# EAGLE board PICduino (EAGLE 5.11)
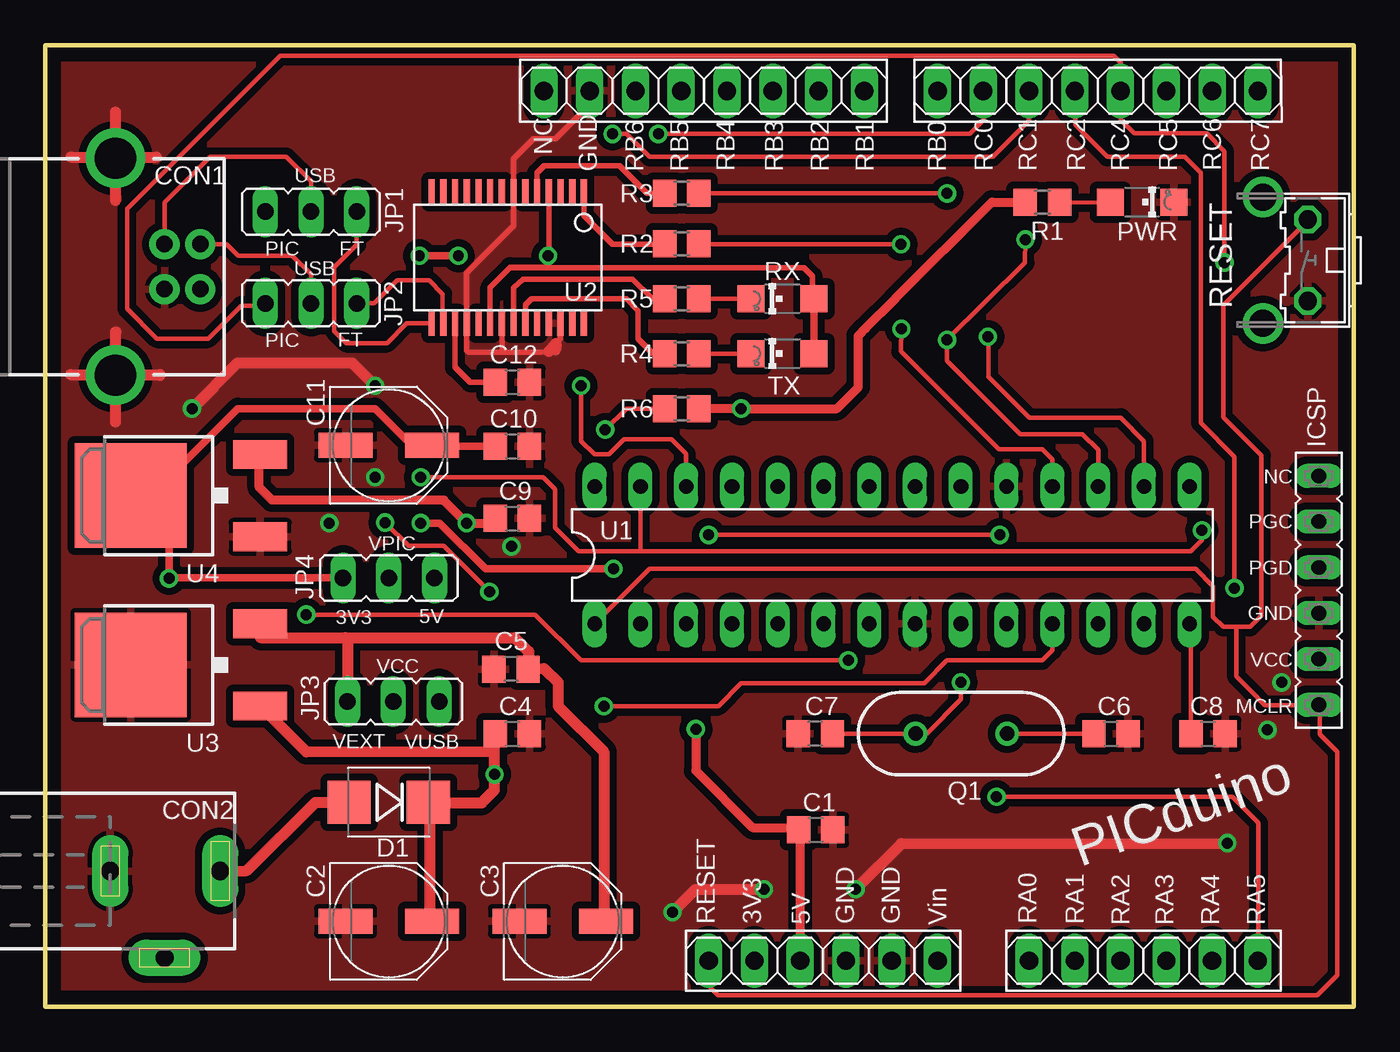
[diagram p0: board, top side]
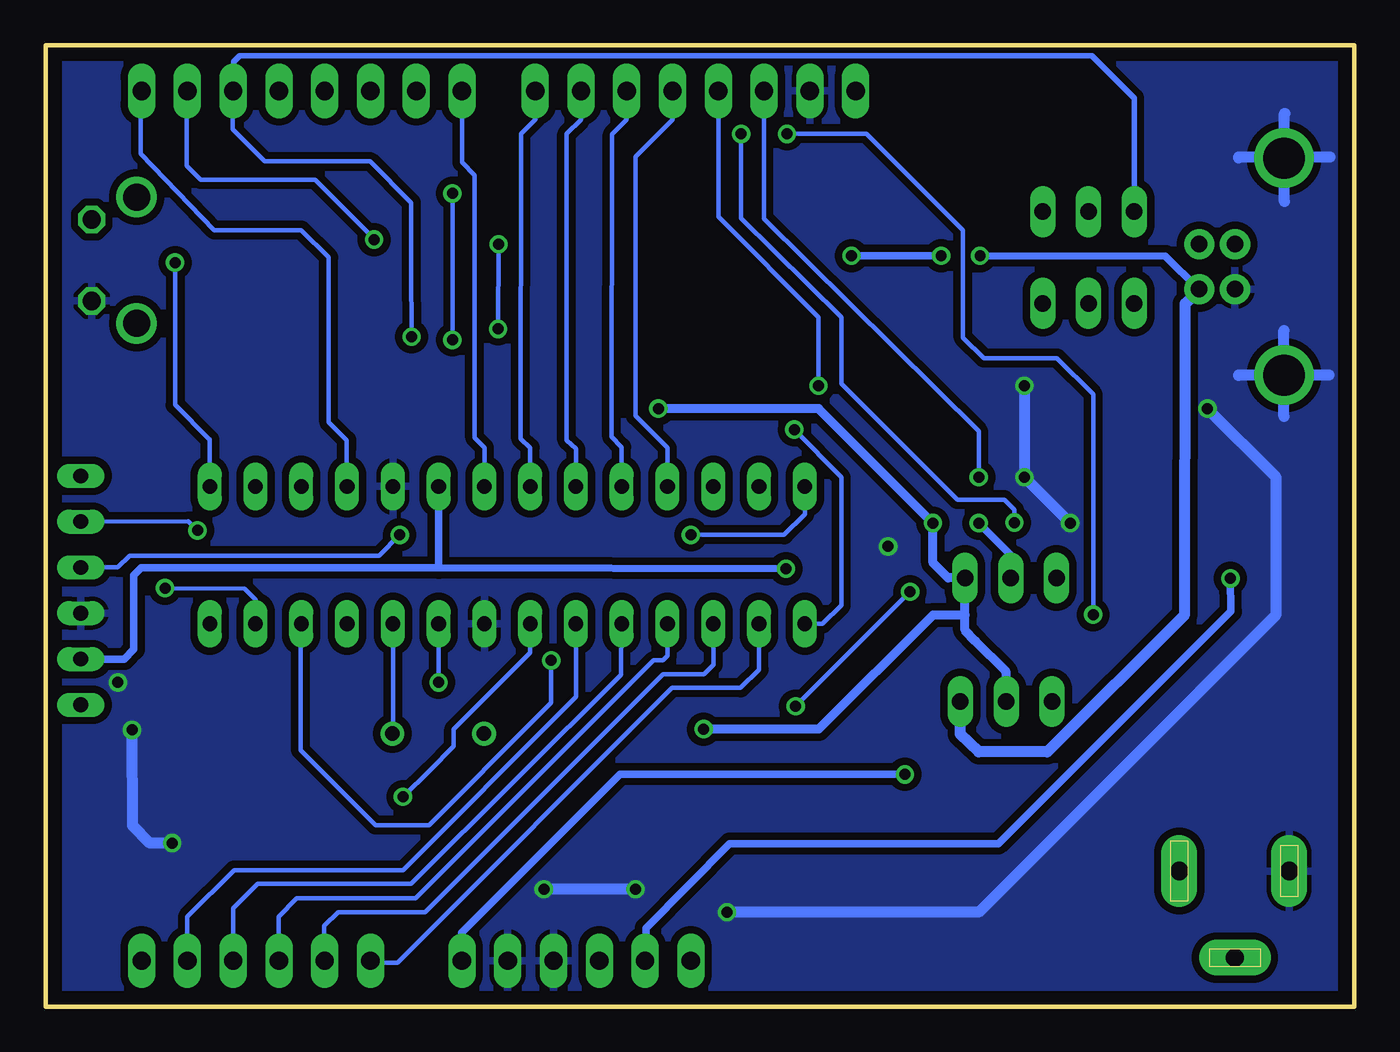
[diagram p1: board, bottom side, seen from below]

Size 72.64 x 53.34 mm. Coordinates in mm from the lower left corner, seen from the top.
Outline: 0,53.34 72.64,53.34 72.64,0 0,0 0,53.34
Copper layers (1*16): Top 0.035mm / dielectric 1.5mm / Bottom 0.035mm
Design rules "default *": minimum track width 10mil, minimum drill 16mil, track to track 8mil, track to pad 8mil, pad to pad 8mil, via to via 8mil, smd to smd 8mil, copper to edge 30mil, drill to drill 8mil, minimum pad ring 10mil, minimum via ring 8mil, stop-mask expansion 4mil, vias tented up to drill 0mil, thermal gap 10mil
Net classes: 0 default: width 0.254 mm, drill 0.305 mm, clearance 0.152 mm; 1 power: width 0.61 mm, drill 0.508 mm, clearance 0.152 mm; 2 gnd: width 0.305 mm, drill 0.508 mm, clearance 0.152 mm; 3 usbvcc: width 0.508 mm, drill 0.508 mm, clearance 0.152 mm; 4 aref: width 0.406 mm

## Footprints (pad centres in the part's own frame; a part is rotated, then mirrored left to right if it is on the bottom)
C0805 = smd 1.3 x 1.5: 1 -0.95,0; 2 0.95,0
PANASONIC_D = smd 3 x 1.4: + 2.4,0; - -2.4,0
USB-B-PTH = drill 0.914 pad 1.676 round: D+ 0,1.25; D- 1.981,1.25; GND 0,-1.25; VBUS 1.981,-1.25 | drill 2.286 round: P$1 -2.718,-6.02; P$2 -2.718,6.02
DCJ0202 = drill 1 pad 2 long: 1 0,3.1; 2 4.8,0; 3 0,-3
SMB-DIODE = smd 2.4 x 2.4: A 2.2,0; C -2.2,0
FE06 = drill 0.813 long: 1 -6.35,0; 2 -3.81,0; 3 -1.27,0; 4 1.27,0; 5 3.81,0; 6 6.35,0
1X08 = drill 1.016 long: 1 -8.89,0; 2 -6.35,0; 3 -3.81,0; 4 -1.27,0; 5 1.27,0; 6 3.81,0; 7 6.35,0; 8 8.89,0
1X06 = drill 1.016 long: 1 -6.35,0; 2 -3.81,0; 3 -1.27,0; 4 1.27,0; 5 3.81,0; 6 6.35,0
JP2 = drill 0.914 long: 1 -2.54,0; 2 0,0; 3 2.54,0
CHIPLED_1206 = smd 1.5 x 1.5: A 0,-1.75; C 0,1.75
HC49US = drill 0.813 round: 1 -2.54,0; 2 2.54,0
R0805 = smd 1.3 x 1.5: 1 -0.95,0; 2 0.95,0
B3F-31XX = drill 1.016 octagon: 1 -2.261,-1.245; 2 2.261,-1.245 | drill 1.499 pad 2.159 round: 3 -3.505,1.245; 4 3.505,1.245
DIL28-3 = drill 0.813 long: 1 -16.51,-3.81; 2 -13.97,-3.81; 3 -11.43,-3.81; 4 -8.89,-3.81; 5 -6.35,-3.81; 6 -3.81,-3.81; 7 -1.27,-3.81; 8 1.27,-3.81; 9 3.81,-3.81; 10 6.35,-3.81; 11 8.89,-3.81; 12 11.43,-3.81; 13 13.97,-3.81; 14 16.51,-3.81; 15 16.51,3.81; 16 13.97,3.81; 17 11.43,3.81; 18 8.89,3.81; 19 6.35,3.81; 20 3.81,3.81; 21 1.27,3.81; 22 -1.27,3.81; 23 -3.81,3.81; 24 -6.35,3.81; 25 -8.89,3.81; 26 -11.43,3.81; 27 -13.97,3.81; 28 -16.51,3.81
SSOP28DB = smd 0.348 x 1.397: 1 -4.225,-3.656; 2 -3.575,-3.656; 3 -2.925,-3.656; 4 -2.275,-3.656; 5 -1.625,-3.656; 6 -0.975,-3.656; 7 -0.325,-3.656; 8 0.325,-3.656; 9 0.975,-3.656; 10 1.625,-3.656; 11 2.275,-3.656; 12 2.925,-3.656; 13 3.575,-3.656; 14 4.225,-3.656; 15 4.225,3.656; 16 3.575,3.656; 17 2.925,3.656; 18 2.275,3.656; 19 1.625,3.656; 20 0.975,3.656; 21 0.325,3.656; 22 -0.325,3.656; 23 -0.975,3.656; 24 -1.625,3.656; 25 -2.275,3.656; 26 -2.925,3.656; 27 -3.575,3.656; 28 -4.225,3.656
DPACK = smd 1.6 x 3: 1 -2.28,-4.8; 3 2.28,-4.8 | smd 5.8 x 6.2: 4 0,2.38

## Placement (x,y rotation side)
C1  100nF  [C0805]  42.77,9.8 0 top
C2  [PANASONIC_D]  19.08,4.72 0 top
C3  [PANASONIC_D]  28.73,4.72 0 top
C4  100nF  [C0805]  25.93,15.14 0 top
C5  100nF  [C0805]  25.86,18.72 180 top
C6  15pF  [C0805]  59.16,15.14 0 top
C7  15pF  [C0805]  42.75,15.14 180 top
C8  100nF  [C0805]  64.54,15.14 0 top
C9  100nF  [C0805]  25.93,27.08 0 top
C10  100nF  [C0805]  25.93,31.09 0 top
C11  [PANASONIC_D]  19.08,31.14 0 top
C12  100nF  [C0805]  25.93,34.65 0 top
CON1  USBPTH  [USB-B-PTH]  6.63,41.05 0 top
CON2  DCJ0202  [DCJ0202]  6.63,7.52 270 top
D1  MBRS130  [SMB-DIODE]  19.08,11.33 180 top
ICSP  [FE06]  70.69,23.09 90 top
J1  [1X08]  58.42,50.8 180 top
J2  [1X06]  60.96,2.54 0 top
J3  [1X08]  36.58,50.8 180 top
JP1  [JP2]  14.76,44.09 180 top
JP2  [JP2]  14.76,39.01 180 top
JP3  [JP2]  19.33,16.92 180 top
JP4  [JP2]  19.08,23.77 0 top
POWER  [1X06]  43.18,2.54 0 top
PWR  [CHIPLED_1206]  60.88,44.63 270 top
Q1  [HC49US]  50.85,15.14 0 top
R1  1k  [R0805]  55.35,44.63 180 top
R2  1k  [R0805]  35.33,42.32 0 top
R3  1k  [R0805]  35.33,45.11 0 top
R4  1k  [R0805]  35.33,36.22 0 top
R5  1k  [R0805]  35.33,39.27 0 top
R6  10k  [R0805]  35.33,33.17 180 top
RESET  RESET  [B3F-31XX]  68.83,41.4 90 top
RX  [CHIPLED_1206]  40.92,39.27 90 top
TX  [CHIPLED_1206]  40.92,36.22 90 top
U1  PIC18F2550_28DIP  [DIL28-3]  47.02,25.04 0 top
U2  FT232RL-BASICSSOP  [SSOP28DB]  25.68,41.55 180 top
U3  LP2950CDT-5.0  [DPACK]  7.14,18.95 90 top
U4  3V3  [DPACK]  7.14,28.35 90 top

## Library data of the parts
C1-C12 R1-R6 = rcl
CON1 D1 Q1 U2 = moja
CON2 = con-jack; OC_FARNELL: unknown; OC_NEWARK: unknown
ICSP = con-lsta; OC_FARNELL: unknown; OC_NEWARK: unknown
J1-J3 POWER = pinhead
JP1-JP4 = jumper
PWR RX TX = led
RESET = switch-omron; MPN: B3F-3100; OC_FARNELL: 959704; OC_NEWARK: 36M3582
U1 = microchip; MF: MICROCHIP; MPN: PIC18F2550-I/SP; OC_FARNELL: 1523822; OC_NEWARK: 80K6054
U3 U4 = v-reg

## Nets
3V3: C10.1 C11.+ JP4.1 POWER.2 U4.4
+5V [usbvcc]: C1.1 C9.1 JP3.2 JP4.3 POWER.3 R6.1 U4.3
AREF: J3.8
D+FT: JP1.1 U2.15
D-FT: JP2.1 U2.16
GND [power]: C1.2 C2.- C3.- C4.2 C5.2 C6.2 C7.2 C8.2 C9.2 C10.2 C11.- C12.2 CON1.GND CON2.3 ICSP.3 J3.7 POWER.4 POWER.5 PWR.C RESET.1 U1.8 U1.19 U2.7 U2.18 U2.21 U2.25 U2.26 U3.4 U4.1
MCLR: ICSP.1 POWER.1 R6.2 RESET.2 U1.1
N$1: C8.1 U1.14
N$2: CON2.1 D1.A
N$3: C3.+ C5.1 JP3.3 U3.3
N$4: CON1.D+ JP1.2
N$5: CON1.D- JP2.2
N$6: R2.1 U2.1
N$8: PWR.A R1.1
N$9: R3.1 U2.5
N$11: R4.1 U2.23
N$12: R5.1 U2.22
N$13: R4.2 TX.C
N$14: C12.1 U2.17
N$15: R5.2 RX.C
RA0: J2.1 U1.2
RA1: J2.2 U1.3
RA2: J2.3 U1.4
RA3: J2.4 U1.5
RA4: J2.5 U1.6
RA5: J2.6 U1.7
RB0: J1.8 U1.21
RB1: J3.1 U1.22
RB2: J3.2 U1.23
RB3: J3.3 U1.24
RB4: J3.4 U1.25
RB5: J3.5 U1.26
RB6: ICSP.5 J3.6 U1.27
RB7: ICSP.4 U1.28
RC0: J1.7 U1.11
RC1: J1.6 U1.12
RC2: J1.5 U1.13
RC4: J1.4 JP2.3 U1.15
RC5: J1.3 JP1.3 U1.16
RC6: J1.2 R3.2 U1.17
RC7: J1.1 R2.2 U1.18
S$2 [usbvcc]: RX.A U2.4 U2.20
S$3 [usbvcc]: R1.2
VCC: ICSP.2 JP4.2 U1.20
VIN: C2.+ C4.1 D1.C POWER.6 U3.1
VUSB: CON1.VBUS JP3.1
X1: C7.1 Q1.1 U1.9
X2: C6.1 Q1.2 U1.10

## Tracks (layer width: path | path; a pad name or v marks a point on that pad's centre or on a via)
3V3  (via drill 0.61)
  Top 0.254: 6.88,26.49 4.34,28.09 U4.4 5.61,28.09 | 20.85,30.63 C11.+
  Top 0.406: 6.88,23.77 6.88,26.49 | 6.88,23.77 JP4.1 | v6.88,23.75 6.88,23.77 | 20.85,30.63 18.31,33.17 10.69,33.17 5.61,28.09 | C10.1 21.53,31.09 C11.+
  Bottom 0.406: v6.88,23.75 6.86,21.92 19.76,9.04 34.67,9.04 39.32,4.34 39.32,3.07 POWER.2
+5V  (via drill 0.61)
  Top 0.508: U4.3 10.69,30.63 11.86,30.61 11.89,30.58 11.89,28.8 12.6,28.09 22.12,28.09 v23.39,26.82 24.66,26.82 C9.1 | 36.09,33.17 R6.1 v38.63,33.17 43.94,33.17 45.14,34.37 45.14,37.21 45.54,37.62 47.17,39.24 | POWER.3 41.88,2.31 41.88,9.93 | 41.88,9.93 C1.1 | 41.88,9.93 39.27,9.93 36.12,13.08 v36.12,15.39
  Bottom 0.508: v38.63,33.17 29.74,33.17 v23.39,26.82 23.39,24.61 22.56,23.77 JP4.3 21.62,21.72 | v36.12,15.39 29.74,15.39 23.39,21.72 21.62,21.72 | 21.62,21.72 21.62,20.88 21.03,20.27 19.38,18.62 19.33,18.54 JP3.2
D+FT
  Top 0.254: JP1.1 17.3,42.27 16.05,41.02 16.05,37.47 16.71,36.8 18.97,36.8 20.07,37.9 U2.15
D-FT
  Top 0.254: JP2.1 18.26,39.01 19.53,40.28 21.31,40.28 22.07,39.52 22.07,37.93 U2.16
GND  (via drill 0.61)
  Top 0.305: J3.7 30.2,50.77 30.23,50.7 29.9,49.68 28.32,48.13 27.1,48.13 26,47.04 U2.7 26,43.33 23.39,40.72 U2.18 23.4,36.39 23.5,36.3 25.37,36.3 | 25.37,36.3 27.51,36.3 27.95,36.34 | U2.21 25.35,36.32 25.37,36.3 | U2.26 28.6,37.04 28.35,36.78
  Top 0.61: v18.31,34.44 17.04,35.71 10.69,35.71 v8.15,33.17 | v34.82,5.23 36.09,6.5 v39.9,6.5 | v44.98,6.5 47.52,9.04 v65.61,9.07 | 28.32,36.42 28.35,36.78 27.95,36.34 | 1.45,47.12 6.17,47.12 | 3.91,44.73 3.91,49.63 | 3.94,37.41 3.91,37.41 3.91,32.44 | 1.42,35.05 6.38,35.05 6.38,35
  Bottom 0.61: v15.77,26.82 v18.31,29.36 v18.31,34.44 | v8.15,33.17 4.34,29.36 4.34,21.74 20.85,5.23 v34.82,5.23 | v39.9,6.5 v44.98,6.5 | v65.61,9.07 66.85,9.07 67.82,10.03 v67.84,15.34 | 3.86,49.53 3.89,49.53 3.89,44.65 | 1.35,47.12 6.43,47.12 6.43,47.07 | 3.91,32.74 3.91,37.52 | 1.42,35.03 6.43,35.03 6.43,35
  other vias: 25.88,25.53 68.63,17.98
  pour Top (isolate 0.406): -0.48,54.86 73.69,54 73.69,-0.61 -2.59,-0.46 -3.86,54.81
  pour Bottom (isolate 0.406): -3.1,54.58 73.69,54 73.69,-0.61 -3.51,-0.64
MCLR  (via drill 0.61)
  Top 0.254: v31.09,32 32.28,33.17 R6.2 | 66.12,21.06 66.12,18.31 66.85,17.58 67.69,16.71 70.54,16.71 ICSP.1 70.74,16.69 70.74,15.11 71.7,14.15 71.7,1.73 70.61,0.64 37.34,0.64 36.83,1.14 POWER.1 | U1.1 33.55,24.28 63.86,24.28 64.82,23.32 64.82,21.62 65.38,21.06 66.12,21.06 | RESET.2 70.08,43.59 65.41,38.91 65.41,32.69 67.51,30.58 67.51,21.69 66.88,21.06 66.12,21.06
  Bottom 0.254: v31.09,32 28.47,29.36 28.47,22.25 29.51,21.23 U1.1
N$1
  Top 0.254: C8.1 63.58,15.34 63.58,20.42 U1.14
N$2
  Top 0.254: 16.69,11.33 D1.A
  Top 0.61: 16.69,11.33 15.01,11.33 11.2,7.54 CON2.1
N$3
  Top 0.254: U3.3 11.96,20.47 | 31.01,5.23 C3.+ | 26.85,18.77 C5.1
  Top 0.61: 16.66,20.47 26.06,20.47 26.85,19.69 26.85,18.77 27.69,18.75 28.47,17.98 28.47,16.66 31.01,14.12 31.01,5.23 | 11.96,20.47 16.66,20.47 | 16.66,20.47 16.79,20.35 JP3.3
N$4
  Top 0.254: JP1.2 14.76,45.8 13.39,47.14 9.17,47.14 6.63,44.63 CON1.D+ 6.63,42.06
N$5
  Top 0.254: JP2.2 14.76,40.61 13.72,41.66 10.72,41.66 10.16,42.21 10.08,42.3 CON1.D-
N$6
  Top 0.305: U2.1 29.9,43.88 31.5,42.29 34.36,42.29 R2.1
N$8
  Top 0.254: R1.1 58.72,44.6 PWR.A 58.95,44.68
N$9
  Top 0.305: U2.5 27.3,46.25 27.69,46.63 31.88,46.63 33.4,45.11 R3.1
N$11
  Top 0.305: R4.1 33.73,36.22 32.92,37.03 32.92,38.61 32.26,39.27 27,39.27 26.67,38.94 26.67,37.91 U2.23
N$12
  Top 0.305: R5.1 33.71,39.27 32.61,40.36 26.52,40.36 26.01,39.88 U2.22
N$13
  Top 0.254: 36.27,36.22 R4.2 TX.C
N$14
  Top 0.305: U2.17 22.75,35.46 23.6,34.62 24.96,34.62 C12.1
N$15
  Top 0.254: 36.09,39.27 R5.2 RX.C
RA0
  Bottom 0.254: U1.2 33.05,18.69 34.06,17.68 37.87,17.68 53.11,2.44 54.51,2.44 J2.1
RA1
  Bottom 0.254: U1.3 35.59,18.95 36.09,18.44 38.38,18.44 51.59,5.23 56.41,5.23 57.18,4.47 57.18,2.57 J2.2
RA2
  Bottom 0.254: U1.4 38.13,19.46 38.38,19.2 38.89,19.2 39.14,18.95 52.1,5.99 58.7,5.99 59.72,4.98 59.72,2.57 J2.3
RA3
  Bottom 0.254: U1.5 40.69,18.54 40.72,18.42 52.35,6.81 60.86,6.81 61.19,6.5 62.23,5.46 J2.4
RA4
  Bottom 0.254: U1.6 43.21,17.2 43.71,16.66 52.81,7.57 62.18,7.57 64.77,4.98 J2.5
RA5  (via drill 0.61)
  Top 0.254: v52.81,11.63 65.89,11.63 67.34,10.19 67.34,2.51 67.41,2.57 J2.6
  Bottom 0.254: v52.81,11.63 51.31,13.11 49.99,14.43 49.99,15.39 45.75,19.63 U1.7
RB0
  Bottom 0.254: U1.21 48.29,31.01 48.82,31.55 48.82,46.13 49.53,46.84 J1.8
RB1
  Bottom 0.254: U1.22 45.75,31.01 46.28,31.5 46.25,48.41 45.44,49.23 J3.1
RB2
  Bottom 0.254: U1.23 43.21,30.94 43.71,31.42 43.71,48.41 42.93,49.2 J3.2
RB3
  Bottom 0.254: U1.24 40.67,31.04 41.22,31.6 41.2,48.39 40.39,49.2 J3.3
RB4
  Bottom 0.254: U1.25 38.13,30.99 39.9,32.77 39.9,47.14 37.85,49.2 J3.4
RB5  (via drill 0.61)
  Top 0.254: v29.74,34.44 29.74,31.37 30.51,30.63 31.29,30.63 32.13,31.47 34.77,31.47 35.59,30.66 U1.26
  Bottom 0.254: v29.74,34.44 29.74,38.25 35.31,43.82 J3.5
RB6  (via drill 0.61)
  Top 0.254: 33.05,25.25 U1.27 33.05,28.88 | 33.05,25.25 63.58,25.25 64.19,25.86 v64.21,26.42 | v20.85,29.36 27.64,29.36 28.3,28.7 28.3,26.57 29.62,25.25 33.05,25.25
  Bottom 0.254: v64.21,26.42 64.72,26.92 ICSP.5 | v20.85,29.36 20.85,31.9 32.77,43.71 J3.6
RB7  (via drill 0.61)
  Top 0.254: v36.83,26.16 v52.98,26.16
  Bottom 0.254: v52.98,26.16 54.13,25.02 67.97,25.02 68.63,24.36 ICSP.4 | v36.83,26.16 31.65,26.16 30.51,27.31 U1.28
RC0  (via drill 0.61)
  Top 0.254: v31.01,16.66 37.36,16.66 38.63,17.93 48.79,17.93 50.06,19.2 55.35,19.2 55.91,19.76 U1.11 | v24.66,23.01 22.12,25.55 20.17,25.55 v18.87,26.85 | v34.04,48.41 51.33,48.41 52.07,49.17 J1.7
  Bottom 0.254: v24.66,23.01 v31.01,16.66 | v18.87,26.85 18.87,27.56 19.43,28.12 22.05,28.12 28.47,34.54 28.47,38.25 34.04,43.74 v34.04,48.41
RC1  (via drill 0.61)
  Top 0.254: v44.58,19.2 29.74,19.2 27.2,21.74 v14.5,21.74 | v31.5,48.41 32.28,48.41 33.55,47.14 52.6,47.14 54.61,49.15 J1.6
  Bottom 0.254: v44.58,19.2 44.58,16.87 45.31,16.13 51.36,10.06 54.33,10.06 58.5,14.22 58.5,19.91 U1.12 | v14.5,21.74 14.5,33.96 16.51,35.97 20.57,35.97 21.72,37.11 21.72,43.05 27.08,48.41 v31.5,48.41
RC2  (via drill 0.61)
  Top 0.254: v66.01,23.22 66.01,30.51 64.14,32.39 64.14,46.25 63.25,47.14 58.95,47.14 57.18,48.92 J1.5
  Bottom 0.254: v66.01,23.22 61.6,23.19 60.99,22.58 U1.13
RC4  (via drill 0.61)
  Top 0.254: v65.46,41.28 65.46,47.45 64.47,48.44 60.45,48.44 59.72,49.17 J1.4 59.72,50.83 59.72,52.35 59.31,52.76 13.06,52.76 4.55,44.25 4.55,38.71 6.2,37.06 9.04,37.06 10.87,38.89 12.04,38.89 12.17,39.01 JP2.3
  Bottom 0.254: v65.46,41.28 65.46,33.38 63.55,31.47 63.53,31.47 U1.15
RC5  (via drill 0.61)
  Top 0.254: v52.32,37.16 52.3,37.19 52.35,37.24 52.35,34.95 54.64,32.66 59.72,32.66 60.99,31.37 U1.16
  Bottom 0.254: v52.32,37.16 52.35,41.05 52.35,44.6 54.64,46.89 60.48,46.89 62.26,48.67 62.26,49.15 J1.3
  Bottom 0.305: JP1.3 12.22,50.39 14.58,52.76 61.87,52.76 62.2,52.43 62.2,50.83 J1.3
RC6  (via drill 0.61)
  Top 0.254: v50.06,45.11 R3.2 36.09,45.11 | U1.17 58.45,30.89 57.58,31.75 54.13,31.75 50.04,35.84 v50.06,36.98 54.38,41.25 v54.41,42.55
  Bottom 0.254: v50.06,45.11 v50.06,36.98 | v54.41,42.55 54.38,42.57 57.68,45.87 64.03,45.87 64.8,46.63 64.8,49.17 J1.2
RC7  (via drill 0.61)
  Top 0.254: v47.5,42.29 36.07,42.29 R2.2 | v47.52,37.59 47.5,36.35 52.93,30.91 55.35,30.91 55.91,30.35 U1.18
  Bottom 0.254: v47.5,42.29 v47.52,37.59 | J1.1 67.36,49.35 67.36,47.32 63.27,43.08 58.95,43.08 58.45,43.08 56.92,41.55 56.92,32.41 55.93,31.42 55.93,30.96 U1.18
S$1
  Top 0.406: 42.67,36.07 42.67,39.4
S$2
  Top 0.305: RX.A 42.6,39.34 42.6,40.51 42.11,41 25.81,41 24.7,39.89 24.7,39.87 | U2.4 27.97,45.2 27.97,41.02 25.81,41.02 24.7,39.87 | U2.20 24.7,39.87
S$3
  Top 0.508: R1.2 52.55,44.63 47.17,39.27
S$4
  Bottom 0.406: 8.66,39.83 10.49,41.63 20.75,41.66
S$6  (via drill 0.6)
  Top 0.406: 20.75,41.66 v20.78,41.66 v22.94,41.66
  Bottom 0.406: v22.94,41.66 v27.91,41.66 27.94,41.66
VCC  (via drill 0.61)
  Top 0.406: v20.85,26.82 21.89,26.82 24.43,24.28 v31.55,24.28
  Bottom 0.406: 50.83,24.33 67.34,24.33 67.74,23.93 67.74,19.81 68.28,19.28 ICSP.2 | 50.83,24.33 U1.20 | JP4.2 19.08,25.04 v20.85,26.82 | v31.55,24.28 50.83,24.33
VIN  (via drill 0.61)
  Top 0.254: 24.94,15.34 C4.1 | 20.85,11.58 D1.C 21.36,10.31 | C2.+ 21.36,5.23 | 11.96,16.66 U3.1
  Top 0.61: 20.85,11.58 20.88,11.35 20.93,11.3 24.23,11.3 24.94,12.01 v24.94,12.88 24.94,14.1 | 24.94,14.1 24.94,15.34 | 21.36,5.23 21.36,10.31 | 11.96,16.66 14.5,14.12 24.94,14.1
  Bottom 0.406: v24.94,12.88 40.77,12.88 49.56,4.09 POWER.6
VUSB
  Bottom 0.61: JP3.1 21.87,15.11 20.85,14.12 17.04,14.12 9.42,21.74 9.4,38.99 CON1.VBUS
X1  (via drill 0.61)
  Top 0.254: v50.83,17.98 50.83,17.04 48.95,15.14 Q1.1 C7.1
  Bottom 0.254: v50.83,17.98 U1.9
X2
  Top 0.254: Q1.2 C6.1
  Bottom 0.254: U1.10 53.37,15.39 Q1.2

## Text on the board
tNames: NC | USB | GND | RB6 | RB5 | RB4 | RB3 | RB2 | RB1 | RB0 | RC0 | RC1 | RC2 | RC4 | RC5 | RC6 | RC7 | PIC | FT | USB | PIC | FT | NC | PGC | VPIC | PGD | GND | 3V3 | 5V | VCC | VCC | MCLR | VEXT | VUSB | PICduino | RESET | 3V3 | 5V | GND | GND | Vin | RA0 | RA1 | RA2 | RA3 | RA4 | RA5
